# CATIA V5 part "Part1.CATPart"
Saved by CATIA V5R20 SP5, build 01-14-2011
Part number: Part1
Bounding box of the stored display mesh (mm): x -40 to 40, y -20 to 20, z 0 to 80
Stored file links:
  D:\Users\matejcekp\Downloads\Catia\Nová složka\Part1.CATPart
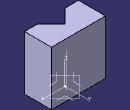
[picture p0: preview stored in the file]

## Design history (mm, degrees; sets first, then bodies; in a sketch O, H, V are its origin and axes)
AxisSystem1: origin (0, 0, 0), X (1, 0, 0), Y (0, 1, 0), Z (0, 0, 1)
Set1
  Plane1: type Offset, RefPlane face of Pad1 from Sketch1.L4, Offset -1, reversed
  Plane2: type Offset, RefPlane face of Pad1 from Sketch1.L5, Offset -1, reversed
Body1 (main body)
  Sketch1 on xy-plane, origin (0, 0, 0), H (1, 0, 0), V (0, 1, 0)
    line L1 (40, 20) -> (-40, 20)
    line L2 (-40, 20) -> (-40, -20)
    line L3 (-40, -20) -> (-20, -20)
    line L4 (-20, -20) -> (0, 0)
    point P5 (0, 0)
    line L5 (0, 0) -> (20, -20)
    point P6 (20, -20)
    line L6 (20, -20) -> (40, -20)
    line L7 (40, -20) -> (40, 20)
    reference projected line E1 through (0, 0) direction (0, 1) from edge [YZ plane of AxisSystem1 | XY plane of AxisSystem1]
    reference projected line E2 through (0, 0) direction (0, 1) from edge [YZ plane of AxisSystem1 | XY plane of AxisSystem1]
    reference projected line E3 through (0, 0) direction (1, 0) from edge [XY plane of AxisSystem1 | ZX plane of AxisSystem1]
    distance E3 L1 = 20
    distance L1 L3 = 40
    angle L4 L5 = 90
    distance L2 L7 = 80
    horizontal: L1 H, L3 H, L6 H
    vertical: L2 V, L7 V
    coincidence: P5 V, P5 H, P6 L3
    symmetry: L7 L2 E1, L4 L5 E2
  Pad1: profile Sketch1, direction (0, 0, 1), length 80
